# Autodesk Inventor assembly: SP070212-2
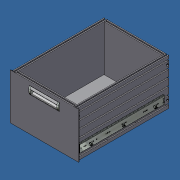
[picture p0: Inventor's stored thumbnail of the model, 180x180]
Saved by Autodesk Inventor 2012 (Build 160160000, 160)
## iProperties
Created: 2012-06
Part Number: SP070212-2
Document SubType Name: Assembly
Designer: Administrator
Author: Administrator
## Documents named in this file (11)
- C:\Andys Backup Data\ANDY'S INVENTOR\INVENTOR LIBRARIES\ASSEMBLY LIBRARY\45 SERIES\DRAWERS\SP070212-2 19X270 DRAWER\SP070212-2 19X270 DRAWER.iam
- C:\Andys Backup Data\ANDY'S INVENTOR\INVENTOR LIBRARIES\ASSEMBLY LIBRARY\45 SERIES\DRAWERS\SP070212-2 19X270 DRAWER\SP070212-2 -1 19X270 WIDTH HORI.ipt
- C:\Andys Backup Data\ANDY'S INVENTOR\INVENTOR LIBRARIES\ASSEMBLY LIBRARY\45 SERIES\DRAWERS\SP070212-2 19X270 DRAWER\SP070212-2 -2 19x270 DEPTH.ipt
- C:\Andys Backup Data\ANDY'S INVENTOR\INVENTOR LIBRARIES\ASSEMBLY LIBRARY\45 SERIES\DRAWERS\SP070212-2 19X270 DRAWER\SP070212-2 -3 19X270 WIDTH BACK.ipt
- C:\Andys Backup Data\ANDY'S INVENTOR\INVENTOR LIBRARIES\PARTS LIBRARY\FASTENING ELEMENTS\SCREWS CAP\21.1200 M8X16.ipt
- C:\Andys Backup Data\ANDY'S INVENTOR\INVENTOR LIBRARIES\PARTS LIBRARY\FASTENING ELEMENTS\NUTS\21.1310_2 M4 SQUARE NUT POS FXG.ipt
- C:\Andys Backup Data\ANDY'S INVENTOR\INVENTOR LIBRARIES\ASSEMBLY LIBRARY\45 SERIES\DRAWERS\SP070212-2 19X270 DRAWER\SP070212-2 -5 bottom panel.ipt
- C:\Andys Backup Data\ANDY'S INVENTOR\INVENTOR LIBRARIES\PARTS LIBRARY\WORKSTATION\32.9805 DRAWER SLIDE 20 HALF.iam
- C:\Andys Backup Data\ANDY'S INVENTOR\INVENTOR LIBRARIES\PARTS LIBRARY\FASTENING ELEMENTS\SCREWS COUNTERSUNK\21.1948 M4X12 CSUNK.ipt
- C:\Andys Backup Data\ANDY'S INVENTOR\INVENTOR LIBRARIES\PARTS LIBRARY\HANDLES LOCKS STOPS\21.9308 FLUSH PULL 160 AL.iam
- C:\Andys Backup Data\ANDY'S INVENTOR\INVENTOR LIBRARIES\PARTS LIBRARY\FASTENING ELEMENTS\BUTTON HEAD FLANGE SCREWS\21.9945 M4X16 BUTTON HEAD FLANGE.ipt
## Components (42 placed, 10 different names)
1. SP070212-2 -1 19X270 WIDTH HORI:1 — Mate:1, Flush:1, Mate:2, Mate:3, Flush:3, Mate:23, Mate:24, Mate:25, Mate:26, Angle:1, Angle:2, Mate:36, Flush:11, Flush:12, Mate:54, Angle:13, Mate:55, Mate:56, Insert:23, Insert:24
2. SP070212-2 -2 19x270 DEPTH:1 — Mate:1, Flush:1, Mate:2, Insert:1, Insert:2, Insert:3, Insert:4, Mate:7, Mate:8, Mate:9, Mate:10, Mate:11, Mate:12, Mate:13, Mate:14, Angle:9, Angle:10, Angle:11, Angle:12, Flush:7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
3. SP070212-2 -2 19x270 DEPTH:2 — Mate:3, Flush:3, Mate:4, Flush:4, Flush:5, Insert:5, Insert:6, Insert:7, Insert:8, Mate:15, Mate:16, Mate:17, Mate:18, Mate:19, Mate:20, Mate:21, Mate:22, Angle:5, Angle:6, Angle:7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
4. SP070212-2 -3 19X270 WIDTH BACK:1 — Mate:4, Flush:4, Flush:5, Mate:27, Mate:28, Mate:29, Mate:30, Angle:3, Angle:4
5. 21.1200 M8 x 16:1 — Insert:1
6. 21.1200 M8 x 16:2 — Insert:2
7. 21.1200 M8 x 16:3 — Insert:3
8. 21.1200 M8 x 16:4 — Insert:5
9. 21.1200 M8 x 16:5 — Insert:4
10. 21.1200 M8 x 16:6 — Insert:6
11. 21.1200 M8 x 16:7 — Insert:8
12. 21.1200 M8 x 16:8 — Insert:7
13. 21.1310_2 M4 SQUARE NUT POS FXG:1 — Mate:23, Mate:24, Angle:2, Mate:53
14. 21.1310_2 M4 SQUARE NUT POS FXG:2 — Mate:11, Mate:12, Angle:9, Mate:45
15. 21.1310_2 M4 SQUARE NUT POS FXG:3 — Mate:13, Mate:14, Angle:11, Mate:43
16. 21.1310_2 M4 SQUARE NUT POS FXG:4 — Mate:7, Mate:8, Angle:10, Mate:44
17. 21.1310_2 M4 SQUARE NUT POS FXG:5 — Mate:9, Mate:10, Angle:12, Mate:42
18. 21.1310_2 M4 SQUARE NUT POS FXG:6 — Mate:25, Mate:26, Angle:1, Mate:52
19. 21.1310_2 M4 SQUARE NUT POS FXG:7 — Mate:29, Mate:30, Angle:4, Mate:46
20. 21.1310_2 M4 SQUARE NUT POS FXG:8 — Mate:27, Mate:28, Angle:3, Mate:47
21. 21.1310_2 M4 SQUARE NUT POS FXG:9 — Mate:17, Mate:18, Angle:7, Mate:49
22. 21.1310_2 M4 SQUARE NUT POS FXG:10 — Mate:21, Mate:22, Angle:6, Mate:50
23. 21.1310_2 M4 SQUARE NUT POS FXG:11 — Mate:19, Mate:20, Angle:5, Mate:51
24. 21.1310_2 M4 SQUARE NUT POS FXG:12 — Mate:15, Mate:16, Angle:8, Mate:48
25. SP070212-2 -5 bottom panel:1 — Flush:7, Insert:11, Insert:12, Insert:13, Insert:14, Insert:15, Insert:16, Insert:17, Insert:18, Insert:19, Insert:20, Insert:21, Insert:22
26. 32.9805 DRAWER SLIDE 20 HALF:1 [sub-assembly] — Mate:35, Flush:12
27. 32.9805 DRAWER SLIDE 20 HALF:2 [sub-assembly] — Mate:33, Mate:34, Flush:11
28. 21.1948 CSUNK M4X12:1 — Insert:11, Mate:42
29. 21.1948 CSUNK M4X12:2 — Insert:12, Mate:43
30. 21.1948 CSUNK M4X12:3 — Insert:13, Mate:44
31. 21.1948 CSUNK M4X12:4 — Insert:14, Mate:45
32. 21.1948 CSUNK M4X12:5 — Insert:15, Mate:46
33. 21.1948 CSUNK M4X12:6 — Insert:16, Mate:47
34. 21.1948 CSUNK M4X12:7 — Insert:17, Mate:48
35. 21.1948 CSUNK M4X12:8 — Insert:18, Mate:49
36. 21.1948 CSUNK M4X12:9 — Insert:19, Mate:50
37. 21.1948 CSUNK M4X12:10 — Insert:20, Mate:51
38. 21.1948 CSUNK M4X12:11 — Insert:21, Mate:52
39. 21.1948 CSUNK M4X12:12 — Insert:22, Mate:53
40. 21.9308 FLUSH PULL 160 AL:1 [sub-assembly] — Mate:54, Angle:13, Mate:55, Mate:56
41. 21.9945 M4X16 BUTTON HEAD FLANGE:1 — Insert:23
42. 21.9945 M4X16 BUTTON HEAD FLANGE:2 — Insert:24
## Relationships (89: Mate 47, Insert 22, Angle 13, Flush 7)
- Mate:1: SP070212-2 -1 19X270 WIDTH HORI:1 ↔ SP070212-2 -2 19x270 DEPTH:1
- Flush:1: SP070212-2 -1 19X270 WIDTH HORI:1 ↔ SP070212-2 -2 19x270 DEPTH:1
- Mate:2: SP070212-2 -1 19X270 WIDTH HORI:1 ↔ SP070212-2 -2 19x270 DEPTH:1
- Mate:3: SP070212-2 -1 19X270 WIDTH HORI:1 ↔ SP070212-2 -2 19x270 DEPTH:2
- Flush:3: SP070212-2 -1 19X270 WIDTH HORI:1 ↔ SP070212-2 -2 19x270 DEPTH:2
- Mate:4: SP070212-2 -2 19x270 DEPTH:2 ↔ SP070212-2 -3 19X270 WIDTH BACK:1
- Flush:4: SP070212-2 -2 19x270 DEPTH:2 ↔ SP070212-2 -3 19X270 WIDTH BACK:1
- Flush:5: SP070212-2 -2 19x270 DEPTH:2 ↔ SP070212-2 -3 19X270 WIDTH BACK:1
- Insert:1: SP070212-2 -2 19x270 DEPTH:1 ↔ 21.1200 M8 x 16:1
- Insert:2: SP070212-2 -2 19x270 DEPTH:1 ↔ 21.1200 M8 x 16:2
- Insert:3: SP070212-2 -2 19x270 DEPTH:1 ↔ 21.1200 M8 x 16:3
- Insert:4: SP070212-2 -2 19x270 DEPTH:1 ↔ 21.1200 M8 x 16:5
- Insert:5: SP070212-2 -2 19x270 DEPTH:2 ↔ 21.1200 M8 x 16:4
- Insert:6: SP070212-2 -2 19x270 DEPTH:2 ↔ 21.1200 M8 x 16:6
- Insert:7: SP070212-2 -2 19x270 DEPTH:2 ↔ 21.1200 M8 x 16:8
- Insert:8: SP070212-2 -2 19x270 DEPTH:2 ↔ 21.1200 M8 x 16:7
- Mate:7: SP070212-2 -2 19x270 DEPTH:1 ↔ 21.1310_2 M4 SQUARE NUT POS FXG:4
- Mate:8: SP070212-2 -2 19x270 DEPTH:1 ↔ 21.1310_2 M4 SQUARE NUT POS FXG:4
- Mate:9: SP070212-2 -2 19x270 DEPTH:1 ↔ 21.1310_2 M4 SQUARE NUT POS FXG:5
- Mate:10: SP070212-2 -2 19x270 DEPTH:1 ↔ 21.1310_2 M4 SQUARE NUT POS FXG:5
- Mate:11: SP070212-2 -2 19x270 DEPTH:1 ↔ 21.1310_2 M4 SQUARE NUT POS FXG:2
- Mate:12: SP070212-2 -2 19x270 DEPTH:1 ↔ 21.1310_2 M4 SQUARE NUT POS FXG:2
- Mate:13: SP070212-2 -2 19x270 DEPTH:1 ↔ 21.1310_2 M4 SQUARE NUT POS FXG:3
- Mate:14: SP070212-2 -2 19x270 DEPTH:1 ↔ 21.1310_2 M4 SQUARE NUT POS FXG:3
- Mate:15: SP070212-2 -2 19x270 DEPTH:2 ↔ 21.1310_2 M4 SQUARE NUT POS FXG:12
- Mate:16: SP070212-2 -2 19x270 DEPTH:2 ↔ 21.1310_2 M4 SQUARE NUT POS FXG:12
- Mate:17: SP070212-2 -2 19x270 DEPTH:2 ↔ 21.1310_2 M4 SQUARE NUT POS FXG:9
- Mate:18: SP070212-2 -2 19x270 DEPTH:2 ↔ 21.1310_2 M4 SQUARE NUT POS FXG:9
- Mate:19: SP070212-2 -2 19x270 DEPTH:2 ↔ 21.1310_2 M4 SQUARE NUT POS FXG:11
- Mate:20: SP070212-2 -2 19x270 DEPTH:2 ↔ 21.1310_2 M4 SQUARE NUT POS FXG:11
- Mate:21: SP070212-2 -2 19x270 DEPTH:2 ↔ 21.1310_2 M4 SQUARE NUT POS FXG:10
- Mate:22: SP070212-2 -2 19x270 DEPTH:2 ↔ 21.1310_2 M4 SQUARE NUT POS FXG:10
- Mate:23: SP070212-2 -1 19X270 WIDTH HORI:1 ↔ 21.1310_2 M4 SQUARE NUT POS FXG:1
- Mate:24: SP070212-2 -1 19X270 WIDTH HORI:1 ↔ 21.1310_2 M4 SQUARE NUT POS FXG:1
- Mate:25: SP070212-2 -1 19X270 WIDTH HORI:1 ↔ 21.1310_2 M4 SQUARE NUT POS FXG:6
- Mate:26: SP070212-2 -1 19X270 WIDTH HORI:1 ↔ 21.1310_2 M4 SQUARE NUT POS FXG:6
- Angle:1: SP070212-2 -1 19X270 WIDTH HORI:1 ↔ 21.1310_2 M4 SQUARE NUT POS FXG:6
- Angle:2: SP070212-2 -1 19X270 WIDTH HORI:1 ↔ 21.1310_2 M4 SQUARE NUT POS FXG:1
- Mate:27: SP070212-2 -3 19X270 WIDTH BACK:1 ↔ 21.1310_2 M4 SQUARE NUT POS FXG:8
- Mate:28: SP070212-2 -3 19X270 WIDTH BACK:1 ↔ 21.1310_2 M4 SQUARE NUT POS FXG:8
- Mate:29: SP070212-2 -3 19X270 WIDTH BACK:1 ↔ 21.1310_2 M4 SQUARE NUT POS FXG:7
- Mate:30: SP070212-2 -3 19X270 WIDTH BACK:1 ↔ 21.1310_2 M4 SQUARE NUT POS FXG:7
- Angle:3: SP070212-2 -3 19X270 WIDTH BACK:1 ↔ 21.1310_2 M4 SQUARE NUT POS FXG:8
- Angle:4: SP070212-2 -3 19X270 WIDTH BACK:1 ↔ 21.1310_2 M4 SQUARE NUT POS FXG:7
- Angle:5: SP070212-2 -2 19x270 DEPTH:2 ↔ 21.1310_2 M4 SQUARE NUT POS FXG:11
- Angle:6: SP070212-2 -2 19x270 DEPTH:2 ↔ 21.1310_2 M4 SQUARE NUT POS FXG:10
- Angle:7: SP070212-2 -2 19x270 DEPTH:2 ↔ 21.1310_2 M4 SQUARE NUT POS FXG:9
- Angle:8: SP070212-2 -2 19x270 DEPTH:2 ↔ 21.1310_2 M4 SQUARE NUT POS FXG:12
- Angle:9: SP070212-2 -2 19x270 DEPTH:1 ↔ 21.1310_2 M4 SQUARE NUT POS FXG:2
- Angle:10: SP070212-2 -2 19x270 DEPTH:1 ↔ 21.1310_2 M4 SQUARE NUT POS FXG:4
- Angle:11: SP070212-2 -2 19x270 DEPTH:1 ↔ 21.1310_2 M4 SQUARE NUT POS FXG:3
- Angle:12: SP070212-2 -2 19x270 DEPTH:1 ↔ 21.1310_2 M4 SQUARE NUT POS FXG:5
- Flush:7: SP070212-2 -2 19x270 DEPTH:1 ↔ SP070212-2 -5 bottom panel:1
- Mate:33: SP070212-2 -2 19x270 DEPTH:2 ↔ 32.9805 DRAWER SLIDE 20 HALF:2
- Mate:34: SP070212-2 -2 19x270 DEPTH:2 ↔ 32.9805 DRAWER SLIDE 20 HALF:2
- Mate:35: SP070212-2 -2 19x270 DEPTH:1 ↔ 32.9805 DRAWER SLIDE 20 HALF:1
- Mate:36: SP070212-2 -1 19X270 WIDTH HORI:1 ↔ SP070212-2 -2 19x270 DEPTH:2
- Flush:11: SP070212-2 -1 19X270 WIDTH HORI:1 ↔ 32.9805 DRAWER SLIDE 20 HALF:2
- Flush:12: SP070212-2 -1 19X270 WIDTH HORI:1 ↔ 32.9805 DRAWER SLIDE 20 HALF:1
- Insert:11: SP070212-2 -5 bottom panel:1 ↔ 21.1948 CSUNK M4X12:1
- Insert:12: SP070212-2 -5 bottom panel:1 ↔ 21.1948 CSUNK M4X12:2
- Insert:13: SP070212-2 -5 bottom panel:1 ↔ 21.1948 CSUNK M4X12:3
- Insert:14: SP070212-2 -5 bottom panel:1 ↔ 21.1948 CSUNK M4X12:4
- Insert:15: SP070212-2 -5 bottom panel:1 ↔ 21.1948 CSUNK M4X12:5
- Insert:16: SP070212-2 -5 bottom panel:1 ↔ 21.1948 CSUNK M4X12:6
- Insert:17: SP070212-2 -5 bottom panel:1 ↔ 21.1948 CSUNK M4X12:7
- Insert:18: SP070212-2 -5 bottom panel:1 ↔ 21.1948 CSUNK M4X12:8
- Insert:19: SP070212-2 -5 bottom panel:1 ↔ 21.1948 CSUNK M4X12:9
- Insert:20: SP070212-2 -5 bottom panel:1 ↔ 21.1948 CSUNK M4X12:10
- Insert:21: SP070212-2 -5 bottom panel:1 ↔ 21.1948 CSUNK M4X12:11
- Insert:22: SP070212-2 -5 bottom panel:1 ↔ 21.1948 CSUNK M4X12:12
- Mate:42: 21.1310_2 M4 SQUARE NUT POS FXG:5 ↔ 21.1948 CSUNK M4X12:1
- Mate:43: 21.1310_2 M4 SQUARE NUT POS FXG:3 ↔ 21.1948 CSUNK M4X12:2
- Mate:44: 21.1310_2 M4 SQUARE NUT POS FXG:4 ↔ 21.1948 CSUNK M4X12:3
- Mate:45: 21.1310_2 M4 SQUARE NUT POS FXG:2 ↔ 21.1948 CSUNK M4X12:4
- Mate:46: 21.1310_2 M4 SQUARE NUT POS FXG:7 ↔ 21.1948 CSUNK M4X12:5
- Mate:47: 21.1310_2 M4 SQUARE NUT POS FXG:8 ↔ 21.1948 CSUNK M4X12:6
- Mate:48: 21.1310_2 M4 SQUARE NUT POS FXG:12 ↔ 21.1948 CSUNK M4X12:7
- Mate:49: 21.1310_2 M4 SQUARE NUT POS FXG:9 ↔ 21.1948 CSUNK M4X12:8
- Mate:50: 21.1310_2 M4 SQUARE NUT POS FXG:10 ↔ 21.1948 CSUNK M4X12:9
- Mate:51: 21.1310_2 M4 SQUARE NUT POS FXG:11 ↔ 21.1948 CSUNK M4X12:10
- Mate:52: 21.1310_2 M4 SQUARE NUT POS FXG:6 ↔ 21.1948 CSUNK M4X12:11
- Mate:53: 21.1310_2 M4 SQUARE NUT POS FXG:1 ↔ 21.1948 CSUNK M4X12:12
- Mate:54: SP070212-2 -1 19X270 WIDTH HORI:1 ↔ 21.9308 FLUSH PULL 160 AL:1
- Angle:13: SP070212-2 -1 19X270 WIDTH HORI:1 ↔ 21.9308 FLUSH PULL 160 AL:1
- Mate:55: SP070212-2 -1 19X270 WIDTH HORI:1 ↔ 21.9308 FLUSH PULL 160 AL:1
- Mate:56: SP070212-2 -1 19X270 WIDTH HORI:1 ↔ 21.9308 FLUSH PULL 160 AL:1
- Insert:23: SP070212-2 -1 19X270 WIDTH HORI:1 ↔ 21.9945 M4X16 BUTTON HEAD FLANGE:1
- Insert:24: SP070212-2 -1 19X270 WIDTH HORI:1 ↔ 21.9945 M4X16 BUTTON HEAD FLANGE:2
